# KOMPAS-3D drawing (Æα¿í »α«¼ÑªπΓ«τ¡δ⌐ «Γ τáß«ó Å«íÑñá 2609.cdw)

Views: Вид 1, Вид 2, Вид 3
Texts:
  Триб промежуточный
  Текст на чертеже
  Размерные надписи
  Шероховатость
  Линия-выноска #1
  Линия-выноска #2
  Линия-выноска #3
  Отклонения формы и база
  Заголовок таблицы
  Ячейка таблицы
  Стрелка вида
  Обозначение изменения
  Фигурная скобка
  Номер узла
  Марка координационной оси
  VRCB
  Выносная надпись
  Обозначение узла
  Марка/позиционное обозначение с линией-выноской
  Марка/позиционное обозначение на линии
  Марка/позиционное обозначение без линии-выноски
  Модуль
  Число зубьев
  Степень точности
  по ГОСТ 13678-73
  Делительный диаметр
  Окружная толщина
  зуба
  Окружной шаг
  Кольцо
  Фреза
  2 Допускается сталь со специальной отделкой поверхности АУ10Е
  ТУ14-1-3390-82
  3  *Размеры обеспечивает инструмент.
  4  Неуказанные предельные отклонения угловых размеров  АТ17 2 ГОСТ
  5  Допускается шероховатость поверхности     зубьев  0,2  при
  химическом полировании.
  Сталь У10А ГОСТ 2283-89
Dimensions and other numbers on the sheet: 7; 0,11; 10; 1,1; 0,116 -0,015; 0,3454; 0,15; 0,8; 1,238; 0,03; 0,45; 0,75; 0,3; 0,18; 2 фаски; 0,9; 0,4; 3,14; 0,26; 2 цапфы; 0,003; 0,02; 0,005; 0,2; 3,74; 0,0835; 0,077; 0,64; 1,6; 1  560-651 HV; 8908-81; 6  Покрытие Хим. Пас.; 1:1; 0.0096г.; 1; 0; 2; 3; 4; 5; 6; 8; 9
